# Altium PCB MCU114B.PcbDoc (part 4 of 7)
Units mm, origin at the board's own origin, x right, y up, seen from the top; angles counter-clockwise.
Board outline 105.51 x 58.76 mm, 8 copper layers (Top Layer, GND 2, Signal Layer 3, Power 4, Power 5, Signal Layer 6, GND 7, Bottom), stack 1.554 mm thick; 444 components, 418 nets, 1811 pads, 981 vias.
Unrouted connection lines stored in the file: 3.
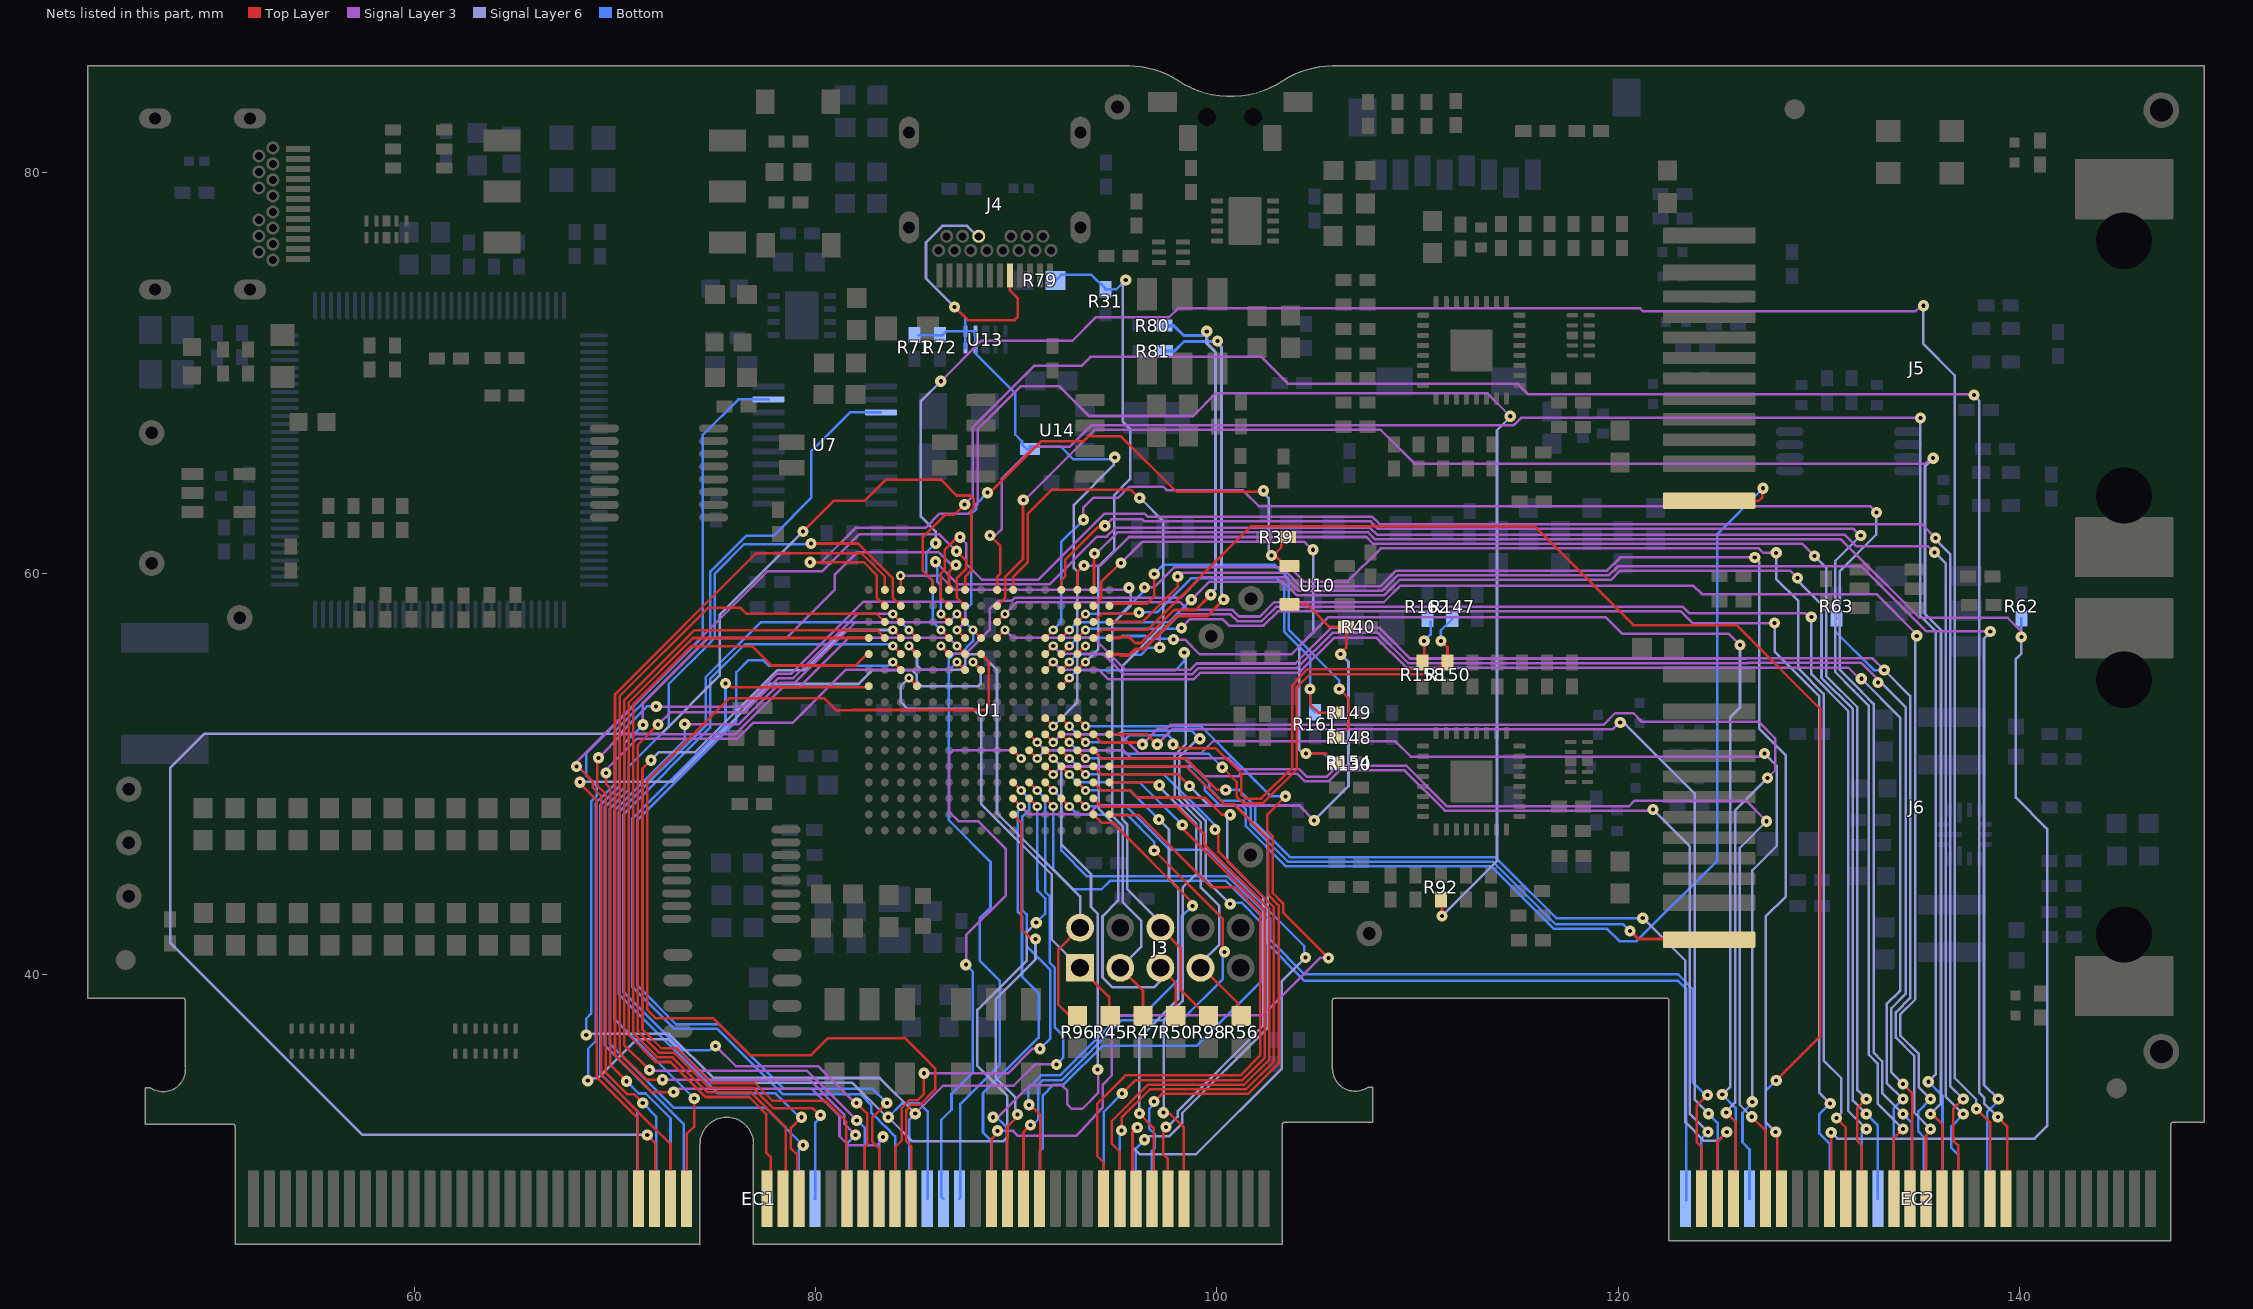
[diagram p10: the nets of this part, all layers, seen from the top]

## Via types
v1: diameter 0.559, hole 0.203, Top Layer to Bottom, tented both sides, 810 vias
v2: diameter 0.457, hole 0.203, Top Layer to Bottom, tented both sides, 153 vias
v3: diameter 0.5, hole 0.2, Top Layer to Bottom, tented both sides, 10 vias
v4: diameter 0.5, hole 0.2, Top Layer to Bottom, tented bottom, 4 vias
v5: diameter 0.5, hole 0.2, Top Layer to Bottom, tented top, 4 vias

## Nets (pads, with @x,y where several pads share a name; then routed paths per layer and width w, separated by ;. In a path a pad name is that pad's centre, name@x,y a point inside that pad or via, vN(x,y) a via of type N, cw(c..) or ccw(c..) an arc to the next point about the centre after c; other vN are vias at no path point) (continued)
MCU_D_N: R81.2 U1.E16 | length 22.7
  Top Layer w0.155: U1.E16@94.641,55.995 95.12,55.995 95.178,55.936 95.61,55.936 95.915,56.241 96.346,56.241 97.989,57.884 99.51,57.884 v1(100.337,58.711)
  Signal Layer 6 w0.155: v1(100.025,71.603) 100.025,71.493 100.236,71.283 100.236,59.004 100.259,58.98 100.259,58.788 v1(100.337,58.711)
  Bottom w0.155: R81.2@97.399,71.099 97.877,71.099 98.356,71.578 100.001,71.578 v1(100.025,71.603)
MCU_D_P: R80.2 U1.D16 | length 22
  Top Layer w0.155: U1.D16@94.641,56.795 95.127,56.795 95.185,56.853 95.61,56.853 95.915,56.549 96.219,56.549 97.862,58.191 98.933,58.191 v1(99.695,58.953)
  Signal Layer 6 w0.155: v1(99.492,72.085) 99.492,71.488 99.835,71.144 99.838,71.144 99.928,71.053 99.928,59.246 99.695,59.013 v1(99.695,58.953)
  Bottom w0.155: R80.2@97.374,72.365 97.851,72.365 98.33,71.886 99.292,71.886 v1(99.492,72.085)
MCU_GPIO0: EC1.49 U1.F8 | length 46.6
  Top Layer w0.127: v1(68.25,49.606) 68.25,49.545 69.075,48.719 69.075,34.907 71.121,32.861 71.121,28.872 EC1.49@71.157,28.836 ; v2(87.841,55.595) U1.F8@88.241,55.195
  Signal Layer 6 w0.127: v1(68.25,49.606) 68.263,49.619 72.829,49.619 77.712,54.503 82.138,54.503 82.824,55.189 84.804,55.189 85.035,54.958 85.035,54.644 85.291,54.389 88.103,54.389 88.235,54.52 88.235,55.201 v2(87.841,55.595)
MCU_GPIO1: EC1.51 U1.A7 | length 92.8
  Top Layer w0.127: v1(71.598,32.02) 71.992,31.627 71.992,28.836 EC1.51@71.957,28.836 ; v1(79.366,62.106) 80.892,63.631 82.436,63.631 83.499,64.694 86.233,64.694 87.026,63.901 87.691,63.901 87.867,63.725 87.867,63.252 87.748,63.133 87.748,60.152 87.441,59.845 U1.A7@87.441,59.195
  Signal Layer 6 w0.127: v1(71.598,32.02) 57.401,32.02 47.803,41.619 47.803,50.317 49.505,52.019 72.314,52.019 75.209,54.915 75.209,57.949 v1(79.366,62.106)
MCU_GPIO2: EC1.53 U1.B7 | length 51.1
  Top Layer w0.127: v1(68.072,50.394) 68.135,50.394 68.872,49.657 68.872,49.352 69.304,48.92 69.304,35.002 71.96,32.346 71.972,32.346 72.757,31.561 EC1.53@72.757,28.836 ; v1(87.016,61.119) 87.511,60.624 87.511,60.268 87.034,59.791 87.034,58.802 U1.B7@87.441,58.395
  Signal Layer 3 w0.127: v1(68.072,50.394) 68.072,50.608 77.581,60.118 80.311,60.118 82.156,61.963 86.163,61.963 87.007,61.119 v1(87.016,61.119)
MCU_GPIO3: EC1.55 U1.C7 | length 43.4
  Top Layer w0.127: EC1.55@73.557,28.836 73.557,32.056 73.939,32.439 v1(73.939,33.833) ; v2(87.041,57.995) U1.C7@87.441,57.595
  Signal Layer 3 w0.127: v1(73.464,52.497) 76.166,52.497 78.235,54.566 78.971,54.566 81.993,57.589 86.635,57.589 v2(87.041,57.995)
  Bottom w0.127: v1(73.464,52.497) 73.464,51.698 69.945,48.179 69.945,37.827 v1(73.939,33.833)
MCU_GPIO4: EC1.50 U1.D7 | length 46.4
  Top Layer w0.127: v2(87.041,57.195) U1.D7@87.441,56.795
  Signal Layer 3 w0.127: v1@72.009,53.365 76.388,53.365 78.046,55.023 78.781,55.023 82.356,58.598 87.238,58.598 87.448,58.389 87.448,57.832 87.449,57.83 87.449,57.603 v2(87.041,57.195)
  Bottom w0.127: EC1.50@71.157,28.836 71.093,28.9 71.093,33.225 69.259,35.059 69.259,48.463 70.218,49.423 70.218,52.019 71.581,53.382 v1(72.041,53.382)
MCU_GPIO5: EC1.52 U1.E7 | length 44.6
  Top Layer w0.127: v1(69.165,50.82) 69.101,50.756 69.101,49.447 69.533,49.015 69.533,35.096 70.577,34.052 70.926,34.052 v1(71.374,33.604) ; v2(87.041,56.395) U1.E7@87.441,55.995
  Signal Layer 3 w0.127: v1(69.165,50.82) 70.346,52.001 70.775,52.001 75.993,52.001 78.33,54.337 79.168,54.337 81.631,56.801 83.678,56.801 86.635,56.801 v2(87.041,56.395)
  Bottom w0.127: v1(71.374,33.604) 72.043,32.935 72.043,28.922 EC1.52@71.957,28.836
MCU_GPIO6: EC1.54 U1.F7 | length 43.2
  Top Layer w0.127: v1(69.545,50.063) 69.545,49.505 69.761,49.289 69.761,35.712 69.761,35.496 v1(70.561,34.696) ; v2(87.041,55.595) U1.F7@87.441,55.195
  Signal Layer 3 w0.127: v1(69.545,50.063) 69.545,50.227 71.09,51.772 76.088,51.772 76.875,52.559 78.848,52.559 81.49,55.201 86.648,55.201 v2(87.041,55.595)
  Bottom w0.127: v1(70.561,34.696) 71.174,34.084 71.523,34.084 72.757,32.85 EC1.54@72.757,28.836
MCU_GPIO7: EC1.56 U1.A6 | length 48
  Top Layer w0.127: U1.A6@86.641,59.195 86.641,60.084 v1(86.991,60.433)
  Signal Layer 3 w0.127: v1(71.38,52.468) 71.38,53.55 74.626,56.795 78.537,56.795 80.95,59.207 80.95,59.967 82.044,61.062 86.142,61.062 86.688,60.516 86.908,60.516 v1(86.991,60.433)
  Bottom w0.127: v1(71.38,52.468) 70.447,51.534 70.447,49.328 69.488,48.369 69.488,36.481 73.406,32.563 73.406,28.987 EC1.56@73.557,28.836
MCU_GPIO8: EC1.57 U1.D1 | length 42.8
  Top Layer w0.127: EC1.57@77.557,28.836 77.749,29.028 77.749,30.928 77.524,31.153 77.524,33.067 76.683,33.909 74.51,33.909 72.765,35.655 72.01,35.655 70.675,36.989 70.675,50.563 70.675,53.588 73.882,56.795 U1.D1@82.641,56.795
MCU_GPIO9: EC1.59 U1.E1 | length 43.1
  Top Layer w0.127: EC1.59@78.357,28.836 78.494,28.973 78.494,32.42 76.777,34.138 74.605,34.138 72.859,35.883 72.105,35.883 70.904,37.084 70.904,50.469 70.904,53.494 73.799,56.388 76.817,56.388 77.783,55.423 81.835,55.423 81.986,55.423 82.45,55.888 82.461,55.888 82.568,55.995 U1.E1@82.641,55.995
MCU_GPIO10: EC1.61 U1.D4 | length 45.7
  Top Layer w0.127: EC1.61@79.157,28.836 79.066,28.927 79.066,31.046 78.761,31.35 78.761,31.456 78.761,32.366 v1(79.295,32.9) ; v2(84.641,57.195) U1.D4@85.041,56.795
  Bottom w0.127: v1(79.295,32.9) 79.178,32.9 77.991,34.087 75.133,34.087 70.173,39.047 70.173,48.085 74.507,52.418 74.507,54.838 77.257,57.589 84.248,57.589 v2(84.641,57.195)
MCU_GPIO11: J3.2 R96.2 U1.E4 | length 26.6
  Top Layer w0.127: v2(84.641,56.395) U1.E4@85.041,55.995 ; R96.2@93.051,38.041 92.569,38.041 92.1,38.509 92.1,41.271 J3.2@93.18,42.351
  Signal Layer 6 w0.127: v2(84.641,56.395) 85.048,55.989 85.048,55.432 85.278,55.201 85.835,55.201 87.204,55.201 87.448,55.444 87.448,55.758 87.678,55.989 88.248,55.989 89.035,55.201 89.035,48.056 93.18,43.911 J3.2@93.18,42.351
MCU_GPIO12: J3.1 R45.1 U1.G4 | length 23.7
  Top Layer w0.127: v2(84.641,54.795) U1.G4@85.041,54.395 ; J3.1@93.18,40.351 94.63,38.902 R45.1@94.63,38.079
  Signal Layer 6 w0.127: v2(84.641,54.795) 84.241,54.395 84.241,53.595 84.571,53.265 87.829,53.265 88.248,52.846 88.248,48.521 91.766,45.002 91.766,41.766 J3.1@93.18,40.351
MCU_GPIO13: J3.3 R47.1 U1.A3 | length 35.6
  Top Layer w0.127: v2(84.226,59.899) 84.226,59.211 U1.A3@84.241,59.195 ; J3.3@95.18,40.351 96.316,39.216 R47.1@96.316,37.942
  Signal Layer 3 w0.127: v2(84.226,59.899) 86.205,59.899 86.907,59.197 95.511,59.197 v1(95.611,59.298)
  Signal Layer 6 w0.127: J3.3@95.18,40.351 96.236,41.407 96.236,42.696 95.299,43.633 95.299,47.418 94.775,47.942 94.775,57.479 95.698,58.401 v1@95.698,59.219
MCU_GPIO14: EC1.62 U1.B3 | length 51.8
  Top Layer w0.127: v1(79.765,61.508) 82.107,61.508 83.832,59.782 83.832,58.804 U1.B3@84.241,58.395
  Bottom w0.127: EC1.62@79.157,28.836 79.157,31.289 v1(79.371,31.503) 77.498,33.376 72.916,33.376 69.716,36.576 69.716,48.274 70.675,49.233 70.675,50.381 72.668,52.374 72.668,53.999 72.669,54 72.669,54.502 74.739,56.572 74.739,56.585 74.968,56.814 74.968,60.008 76.434,61.474 79.682,61.474 v1@79.698,61.458
MCU_GPIO15: EC1.64 U1.C3 | length 45.4
  Top Layer w0.127: v1(72.136,52.476) 71.133,51.473 71.133,50.374 71.133,37.179 72.199,36.112 72.954,36.112 74.7,34.366 76.872,34.366 77.894,33.344 79.86,33.344 80.203,33.001 v1(80.234,33.001) ; v2(83.841,57.995) U1.C3@84.241,57.595
  Signal Layer 3 w0.127: v1(72.136,52.476) 72.746,53.086 76.432,53.086 78.14,54.795 78.876,54.795 82.076,57.995 v2(83.841,57.995)
  Bottom w0.127: EC1.64@79.957,28.836 79.968,28.846 79.968,32.618 80.234,32.885 v1(80.234,33.001)
MCU_GPIO16: EC1.67 U1.D3 | length 44.8
  Top Layer w0.127: v1(71.78,50.698) 71.361,50.279 71.361,37.273 72.294,36.341 73.049,36.341 74.794,34.595 76.967,34.595 77.83,33.731 80.47,33.731 81.527,32.674 81.527,28.866 EC1.67@81.557,28.836 ; v2(83.841,57.195) U1.D3@84.241,56.795
  Signal Layer 6 w0.127: v1(71.78,50.698) 72.187,51.105 73.991,51.105 78.081,55.194 79.452,55.194 81.453,57.195 v2(83.841,57.195)
MCU_GPIO17: EC1.69 U1.E3 | length 47
  Top Layer w0.127: v1(82.038,33.611) 82.558,33.09 82.558,31.554 82.431,31.427 82.431,28.91 EC1.69@82.357,28.836 ; v2(83.841,56.395) U1.E3@84.241,55.995
  Signal Layer 3 w0.127: v1(75.006,36.449) 76.01,35.446 80.113,35.446 81.948,33.611 v1(82.038,33.611)
  Bottom w0.127: v1(75.006,36.449) 74.919,36.449 74.716,36.246 73.297,36.246 70.402,39.141 70.402,47.99 74.735,52.323 74.735,54.743 76.476,56.484 83.602,56.484 83.628,56.458 83.778,56.458 v2(83.841,56.395)
MCU_GPIO18: EC1.71 U1.F3 | length 46.5
  Top Layer w0.127: EC1.71@83.157,28.836 83.157,31.337 82.825,31.668 82.825,32.889 v1(83.541,33.604) ; v2(83.841,55.595) U1.F3@84.241,55.195
  Bottom w0.127: v1(83.541,33.604) 82.835,34.31 78.415,34.31 75.189,37.535 73.043,37.535 71.088,39.491 71.088,47.706 76.043,52.661 76.043,55.088 76.651,55.696 77.37,55.696 77.65,55.417 83.602,55.417 83.78,55.595 v2(83.841,55.595)
MCU_GPIO19: R92.2 U1.B2 | length 74.7
  Top Layer w0.127: v1(79.722,60.571) 82.396,60.571 83.051,59.917 83.051,59.033 83.051,58.785 U1.B2@83.441,58.395
  Top Layer w0.159: v1(111.222,42.933) 111.222,43.741 R92.2@111.247,43.766
  Signal Layer 3 w0.127: v1(79.722,60.571) 80.273,60.571 81.982,62.281 85.46,62.281 86.178,62.999 87.614,62.999 88.07,63.455 88.07,67.191 90.217,69.338 92.149,69.338 93.624,67.863 98.821,67.863 99.964,69.006 113.47,69.006 v1(114.626,67.85)
  Signal Layer 6 w0.127: v1(111.222,42.933) 113.966,45.676 113.966,67.154 114.626,67.814 v1(114.626,67.85)
MCU_GPIO20: EC1.68 U1.C2 | length 50.2
  Top Layer w0.127: v1(72.365,34.773) 71.552,34.773 70.293,36.032 70.218,36.106 70.218,53.778 70.224,53.783 70.224,53.892 74.625,58.293 76.251,58.293 76.539,58.004 83.032,58.004 U1.C2@83.441,57.595
  Signal Layer 3 w0.127: v1(72.365,34.773) 79.681,34.773 81.41,33.043 81.41,32.588 v1(81.986,32.011)
  Bottom w0.127: EC1.68@81.557,28.836 81.557,31.582 v1(81.986,32.011)
MCU_GPIO21: EC1.70 U1.D2 | length 49.1
  Top Layer w0.127: v1(71.704,35.255) 70.447,36.513 70.447,53.683 73.949,57.185 83.051,57.185 U1.D2@83.441,56.795
  Signal Layer 3 w0.127: v1(71.704,35.255) 71.742,35.217 79.56,35.217 80.15,34.627 v1(82.044,32.733)
  Bottom w0.127: v1(82.044,32.733) 82.091,32.733 82.431,32.392 82.431,28.91 EC1.70@82.357,28.836
MCU_GPIO22: EC1.72 U1.A2 | length 54.8
  Top Layer w0.127: v1(72.914,34.157) 71.844,34.157 69.99,36.011 69.99,36.614 69.99,53.981 77.031,61.023 82.268,61.023 83.441,59.849 U1.A2@83.441,59.195
  Signal Layer 3 w0.127: v1(72.914,34.157) 73.031,34.157 73.19,34.315 79.815,34.315 81.182,32.948 81.182,31.952 81.631,31.503 83.029,31.503 83.347,31.821 v1(83.347,31.923)
  Bottom w0.127: EC1.72@83.157,28.836 83.157,31.733 v1(83.347,31.923)
MCU_GPIO23: EC1.74 U1.G1 | length 43.8
  Top Layer w0.127: v1(75.499,54.53) 75.616,54.53 75.811,54.335 82.431,54.335 82.438,54.343 82.589,54.343 U1.G1@82.641,54.395
  Bottom w0.127: v1(75.499,54.53) 75.499,52.44 70.859,47.8 70.859,39.396 72.949,37.307 75.094,37.307 78.345,34.056 82.222,34.056 82.758,33.519 82.758,33.14 83.168,32.73 83.168,32.716 83.428,32.455 83.443,32.455 83.957,31.941 EC1.74@83.957,28.836
MCU_GPIO24: EC1.75 U1.E8 | length 56.9
  Top Layer w0.127: EC1.75@84.757,28.836 84.757,31.451 84.514,31.693 84.514,33.262 84.775,33.522 85.186,33.522 85.954,34.29 85.954,35.336 85.389,35.9 84.447,36.842 80.607,36.842 79.763,35.999 76.727,35.999 74.892,37.833 72.033,37.833 71.59,38.277 71.59,49.695 75.694,53.799 80.415,53.799 81.012,53.201 81.83,53.201 81.833,53.204 88.403,53.204 88.632,53.433 88.632,55.604 U1.E8@88.241,55.995
MCU_GPIO25: J3.6 R98.2 U1.A10 | length 39.3
  Top Layer w0.127: U1.A10@89.841,59.195 89.841,59.845 90.559,60.563 90.559,62.967 91.785,64.193 95.693,64.193 v1@96.197,63.689 ; J3.6@97.18,42.351 98.208,41.324 98.208,39.244 R98.2@99.372,38.079
  Signal Layer 6 w0.127: v1@96.197,63.689 96.258,63.689 97.319,62.628 97.319,57.43 95.291,55.402 95.291,47.749 95.528,47.513 95.528,44.274 96.94,42.861 96.94,42.315 J3.6@97.166,42.089
  other v1: 96.15,63.779
MCU_GPIO26: J3.5 R50.1 U1.L11 | length 22.3
  Top Layer w0.127: U1.L11@90.641,51.195 v2(91.041,50.795) ; J3.5@97.18,40.351 97.949,39.583 R50.1@97.949,37.942
  Signal Layer 6 w0.127: v2(91.041,50.795) 91.448,51.201 93.848,51.201 94.115,50.934 94.115,48.279 95.071,47.324 95.071,43.696 94.295,42.92 94.295,39.868 94.786,39.377 96.871,39.377 97.18,39.686 J3.5@97.18,40.351
MCU_GPIO27: J3.7 R56.1 U1.G13 | length 27.9
  Top Layer w0.127: U1.G13@92.241,54.395 v2(92.641,54.795) ; J3.7@99.18,40.351 99.275,40.351 101.069,38.558 101.069,38.088 R56.1@101.215,37.942
  Signal Layer 6 w0.127: v1(98.37,56.065) 98.448,55.986 98.448,51.501 97.892,50.944 97.892,48.923 98.256,48.559 99.205,47.61 99.205,44.355 100.123,43.438 100.123,42.552 ; J3.7@99.166,40.089 99.166,40.565 100.122,41.521 100.122,42.551
  Bottom w0.127: v2(92.641,54.795) 93.033,55.187 93.277,55.187 93.278,55.189 97.297,55.189 ; 97.297,55.188 97.93,55.188 98.37,55.628 v1(98.37,56.065)
MCU_GPIO28: EC1.76 U1.N11 U7.9 | length 82.2
  Top Layer w0.127: U1.N11@90.641,49.595 v2(91.041,49.195)
  Signal Layer 3 w0.127: v1(84.959,33.078) 86.352,34.471 89.865,34.471 90.929,35.535 v1(91.999,35.535)
  Signal Layer 6 w0.127: v1(68.555,37.008) 68.605,37.059 72.69,37.059 74.893,34.856 83.181,34.856 v1(84.959,33.078)
  Bottom w0.127: v1(68.555,37.008) 68.555,37.816 68.802,38.063 68.802,48.653 69.075,48.926 69.075,49.409 68.555,49.93 68.555,51.047 74.371,56.864 74.371,66.929 76.138,68.696 U7.9@77.642,68.696 ; EC1.76@84.757,28.836 84.667,28.926 84.667,32.786 v1(84.959,33.078) ; v2(91.041,49.195) 91.435,48.801 91.435,44.772 ; 91.437,44.772 91.437,44.144 91.67,43.911 91.67,40.598 91.923,40.345 91.923,37.373 92.342,36.953 92.342,35.878 v1(91.999,35.535)
MCU_GPIO29: EC1.78 U1.P11 U7.13 | length 90.8
  Top Layer w0.127: U1.P11@90.641,48.795 v2(91.041,48.395)
  Signal Layer 6 w0.127: v1@68.656,34.849 69.134,34.849 71.065,36.779 72.647,36.779 74.799,34.627 81.815,34.627 83.543,32.9 v1(83.613,32.9) 84.819,31.693 85.956,31.693 89.331,31.693 89.557,31.92 89.557,33.964 88.062,35.459 88.062,38.252 90.51,40.701 90.51,42.118 v1(90.992,42.6)
  Bottom w0.127: v1@68.656,34.849 68.656,36.322 69.03,36.696 69.03,48.558 69.99,49.517 69.99,52.159 74.739,56.909 74.739,60.102 76.528,61.891 77.881,61.891 79.781,63.791 79.781,66.116 81.711,68.046 U7.13@83.242,68.046 ; v1(83.613,32.9) 84.298,33.586 85.188,33.586 85.581,33.192 85.581,32.005 85.581,28.86 EC1.78@85.557,28.836 ; v1(90.992,42.6) 91.441,43.049 91.441,43.816 91.056,44.202 91.056,44.711 91.05,44.717 91.05,48.386 v2(91.041,48.395)
  other v1: 68.631,34.722
MCU_GPIO30: EC1.80 U1.L10 | length 30
  Top Layer w0.127: U1.L10@89.841,51.195 v2(90.241,50.795)
  Signal Layer 3 w0.127: v1@87.499,40.469 87.499,41.983 89.48,43.964 89.48,46.267 88.083,47.664 87.11,47.664 86.648,48.126 86.648,50.996 86.841,51.189 89.848,51.189 v2(90.241,50.795)
  Bottom w0.127: EC1.80@86.357,28.836 86.256,28.937 86.256,32.764 86.766,33.274 86.766,34.061 87.833,35.128 87.833,40.155 v1(87.481,40.507)
MCU_GPIO31: EC1.82 R39.1 U1.D8 U10.1 | length 61.2
  Top Layer w0.127: v2(87.841,57.195) U1.D8@88.241,56.795 ; v1(88.566,64.04) 88.691,64.04 91.257,66.607 93.347,66.607 93.593,66.853 95.227,66.853 97.992,64.087 102.271,64.087 v1(102.325,64.141) ; v1(102.718,60.909) v1@102.808,60.909 ; R39.1@103.543,61.689 103.444,61.689 103.208,61.452 103.208,61.309 v1@102.808,60.909 ; U10.1@103.625,60.378 103.425,60.378 102.977,60.827 102.891,60.827 v1@102.808,60.909
  Signal Layer 6 w0.127: v1(102.325,64.141) 102.325,64.024 102.593,63.756 102.593,61.151 102.718,61.026 v1(102.718,60.909)
  Bottom w0.127: EC1.82@87.157,28.836 87.207,28.885 87.207,33.562 89.179,35.535 89.179,36.829 ; v1(88.566,64.04) 88.007,63.481 88.007,63.227 87.753,62.973 87.753,58.477 87.448,58.172 87.448,57.589 v2(87.841,57.195) 87.841,56.638 87.204,56.001 86.891,56.001 86.635,55.745 86.635,47.708 88.712,45.631 88.712,43.363 88.185,42.836 88.185,40.695 89.179,39.7 89.179,39.588 ; 89.18,36.83 89.18,39.587
MCU_GPIO32: EC1.85 U1.J14 | length 47.9
  Top Layer w0.127: EC1.85@88.784,28.923 88.784,31.84 89.065,32.121 v1(89.065,32.224) ; U1.J14@93.041,52.795 v2(93.441,52.395) ; v1@103.577,49.054 102.514,47.992 102.514,47.177 102.794,46.897 102.794,44.069 103.302,43.561 103.302,43.104 v1(105.56,40.846)
  Signal Layer 3 w0.127: v1(89.065,32.224) 89.071,32.217 89.832,32.217 90.077,31.973 92.984,31.973 93.218,32.207 94.277,33.356 94.31,33.393 94.31,34.537 94.767,34.994 94.767,37.578 95.17,37.98 102.282,37.98 105.147,40.846 v1(105.56,40.846)
  Bottom w0.127: v2(93.441,52.395) 99.2,52.395 101.248,50.347 101.248,50.339 101.896,49.691 101.905,49.691 102.694,48.902 v1@103.526,48.902
  other v1: 103.425,48.902
MCU_GPIO33: EC1.87 U1.R10 | length 21.4
  Top Layer w0.127: EC1.87@89.557,28.836 89.557,32.432 v1@90.173,33.048 ; U1.R10@89.841,47.995 90.241,47.595 90.241,42.298 v1@90.852,41.688
  Signal Layer 6 w0.127: v1@90.139,33.04 90.139,33.132 89.941,33.33 89.941,33.903 88.984,34.86 88.984,38.794 90.955,40.764 v1(90.955,41.792) ; v1@90.189,33.131 v1@90.267,33.052
  other v1: 90.061,33.039
MCU_GPIO34: EC1.86 R40.1 U1.P10 U10.3 | length 51.1
  Top Layer w0.127: U1.P10@89.841,48.795 v2(90.241,48.395) ; U10.3@103.625,58.478 104.499,58.478 105.624,57.353 R40.1@106.443,57.353 106.443,56.318 106.172,56.048 v1(106.172,55.989)
  Signal Layer 3 w0.127: v2(90.241,48.395) 90.635,48.001 93.604,48.001 94.048,48.445 104.108,48.445 v1(104.851,47.701)
  Signal Layer 6 w0.127: v1(104.851,47.701) 106.561,49.411 106.561,55.6 v1(106.172,55.989)
  Bottom w0.127: EC1.86@88.757,28.836 88.757,31.72 88.338,32.139 88.338,34.098 91.11,36.87 91.11,39.091 90.282,39.919 90.282,42.921 90.076,43.126 90.076,48.155 90.241,48.32 v2(90.241,48.395)
MCU_GPIO35: EC1.73 U1.N10 | length 27.9
  Top Layer w0.127: EC1.73@83.957,28.836 83.957,31.416 84.286,31.744 84.286,33.356 84.68,33.751 85.091,33.751 85.389,34.049 v1(85.389,35.092) ; U1.N10@89.841,49.595 v2(90.241,49.195)
  Signal Layer 3 w0.127: v1(85.389,35.092) 89.575,35.092 90.787,36.304 91.173,36.304 v1(91.183,36.314)
  Bottom w0.127: v2(90.241,49.195) 90.635,48.801 90.635,48.558 90.635,48.232 90.305,47.902 90.305,43.221 90.51,43.015 90.51,42.311 90.51,41.434 91.694,40.25 91.694,36.825 v1(91.183,36.314)
MCU_GPIO36: EC2.122 U1.P12 | length 49.2
  Top Layer w0.127: U1.P12@91.441,48.795 v2(91.841,48.395)
  Bottom w0.127: v2(91.841,48.395) 91.841,45.25 92.815,44.277 94.259,44.277 94.666,44.683 100.462,44.683 102.438,42.707 102.438,41.637 104.375,39.7 123.001,39.7 123.39,39.311 EC2.122@123.39,28.77
MCU_GPIO37: EC2.123 U1.N12 | length 49.8
  Top Layer w0.127: U1.N12@91.441,49.595 v2(91.841,49.195) ; EC2.123@124.182,28.923 124.182,31.396 123.922,31.655 123.922,33.473 v1(124.46,34.011)
  Bottom w0.127: v2(91.841,49.195) 92.241,48.795 92.241,46.196 93.526,44.912 100.556,44.912 102.667,42.802 102.667,41.732 104.377,40.022 123.002,40.022 123.719,39.305 123.719,34.659 124.368,34.011 v1(124.46,34.011)
MCU_GPIO38: EC2.124 U1.M12 | length 52.6
  Top Layer w0.127: U1.M12@91.441,50.395 v2(91.841,49.995)
  Signal Layer 3 w0.127: v2(91.841,49.995) 92.235,50.389 98.845,50.389 99.329,49.905 101.082,49.905 101.209,50.032 104.001,50.032 104.387,49.647 105.553,49.647 106.104,50.197 109.354,50.197 111.363,48.189 121.482,48.189 v1@121.509,48.216
  Signal Layer 6 w0.127: v1(121.738,48.241) 123.585,46.394 123.585,33.059 v1(124.481,32.163)
  Bottom w0.127: EC2.124@124.155,28.836 124.155,31.837 v1(124.481,32.163)
MCU_GPIO39: EC1.88 U1.L12 | length 29.5
  Top Layer w0.127: U1.L12@91.441,51.195 v2(91.841,50.795)
  Signal Layer 3 w0.127: v1@89.058,32.911 89.086,32.911 90.663,34.487 92.28,34.487 92.541,34.227 92.541,33.545 92.761,33.325 93.294,33.325 94.082,34.112 94.082,35.255 v1(94.056,35.281)
  Signal Layer 6 w0.127: v2(91.841,50.795) 92.248,50.389 92.248,46.493 93.722,45.019 93.722,43.386 94.066,43.042 94.066,35.29 v1(94.056,35.281)
  Bottom w0.127: v1(88.838,32.901) 89.016,32.901 89.382,32.535 89.521,32.397 89.521,28.872 EC1.88@89.557,28.836
MCU_GPIO40: EC1.89 U1.P13 | length 31.3
  Top Layer w0.127: EC1.89@90.357,28.836 90.357,32.163 v1(90.707,32.512) ; U1.P13@92.241,48.795 v2(92.641,48.395) ; v1(96.876,46.203) 100.295,42.783 100.295,41.438 100.298,41.435 100.298,41.231 v1(100.381,41.148)
  Bottom w0.127: v1@90.759,32.459 91.093,32.793 91.093,34.518 91.329,34.754 92.267,34.754 95.252,37.739 98.246,37.739 100.295,39.788 100.295,41.062 v1(100.381,41.148) ; v2(92.641,48.395) 93.049,47.987 95.523,47.987 96.876,46.634 v1(96.876,46.203)
MCU_GPIO41: EC1.91 U1.R15 | length 26.2
  Top Layer w0.127: v1@90.567,33.642 91.194,33.015 91.194,28.873 EC1.91@91.157,28.836 ; U1.R15@93.841,47.995 94.251,47.585 94.803,47.585 v1@98.694,43.695
  Bottom w0.127: v1@90.594,33.535 90.594,34.342 91.235,34.983 92.172,34.983 95.158,37.968 96.297,37.968 98.236,39.907 98.236,42.901 v1(98.776,43.441)
  other v1: 90.625,33.519
MCU_GPIO44: J4.A5 J4.B5 R71.2 R72.2 U1.J12 U13.4 U13.5 U13.6 U13.7 U14.4 | length 44.9
  Top Layer w0.127: v1(86.919,73.304) 87.579,72.644 89.916,72.644 90.068,72.796 90.068,73.736 89.675,74.129 J4.A5@89.675,74.866 ; U1.J12@91.441,52.795 v2(91.841,52.395)
  Signal Layer 6 w0.127: v1(86.919,73.304) 85.496,74.727 85.496,76.526 86.161,77.19 86.312,77.341 87.539,77.341 88.054,76.826 J4.B5@88.125,76.826 ; v2(91.841,52.395) 93.048,53.601 93.048,60.098 92.871,60.275 92.871,63.432 94.854,65.416 94.854,65.695 v1@94.92,65.761
  Bottom w0.127: R71.2@85.105,71.896 86.324,71.896 86.513,72.085 U13.6@87.46,72.085 ; v1(86.919,73.304) 87.46,72.763 U13.6@87.46,72.085 ; U13.5@87.46,71.25 U13.6@87.46,72.085 ; U14.4@90.518,66.208 90.282,66.444 90.282,66.6 89.954,66.928 89.954,68.993 87.997,70.95 87.997,71.214 U13.4@87.96,71.25 U13.7@87.96,72.085 U13.6@87.46,72.085 ; U14.4@90.675,66.208 90.675,66.332 92.215,66.332 92.83,65.717 94.876,65.717 v1@94.92,65.761
  other v1: 94.907,65.802
MCU_GPIO45: EC1.92 U1.J13 | length 40.6
  Top Layer w0.127: U1.J13@92.241,52.795 v2(92.641,52.395)
  Signal Layer 6 w0.127: v1(99.147,51.768) 99.038,51.768 98.12,50.85 98.12,49.018 99.434,47.704 99.434,44.762 v1(100.66,43.536)
  Bottom w0.127: EC1.92@91.157,28.836 91.157,31.206 91.321,31.37 91.321,33.994 91.853,34.525 92.362,34.525 94.311,36.474 99.009,36.474 102.177,39.642 102.177,42.645 101.219,43.603 100.727,43.603 v1(100.66,43.536) ; v2(92.641,52.395) 93.035,52.001 95.126,52.001 95.291,52.166 98.749,52.166 v1(99.147,51.768)
MCU_GPIO46: R31.2 R79.1 U1.F14 | length 24.9
  Top Layer w0.127: U1.F14@93.041,55.195 v2(93.441,55.595)
  Signal Layer 6 w0.127: v2(93.441,55.595) 94.077,56.231 94.077,60.343 94.872,61.138 94.872,63.909 95.678,64.715 95.678,67.208 95.311,67.574 95.311,68.546 95.313,68.548 95.313,68.917 95.311,68.919 95.311,74.392 95.453,74.534 v1(95.453,74.651)
  Bottom w0.127: R79.1@91.956,74.621 92.24,74.905 93.744,74.905 94.437,74.211 R31.2@94.437,74.184 94.986,74.184 v1(95.453,74.651)
MCU_GPIO47: U1.E14 | length 0.6
  Top Layer w0.127: U1.E14@93.041,55.995 v2(93.441,56.395)
MCU_GPIO48: EC1.99 U1.R16 | length 30.7
  Top Layer w0.127: EC1.99@94.357,28.836 94.357,30.636 94.037,30.956 94.037,33.578 95.442,34.983 101.174,34.983 102.159,35.968 102.159,43.087 100.872,44.374 99.709,44.374 96.121,47.962 94.674,47.962 U1.R16@94.641,47.995
MCU_GPIO49: EC1.101 U1.P15 | length 32
  Top Layer w0.127: U1.P15@93.841,48.795 94.251,48.385 97.995,48.385 99.361,47.02 99.361,46.532 102.616,43.277 102.616,35.779 101.363,34.525 96.567,34.525 94.767,32.726 94.767,31.575 95.157,31.185 EC1.101@95.157,28.836
MCU_GPIO50: EC1.103 U1.P14 | length 35.1
  Top Layer w0.127: U1.P14@93.041,48.795 v2(93.441,48.395) ; EC1.103@95.957,28.836 95.792,29.001 95.792,32.151 v1(96.033,32.392)
  Signal Layer 6 w0.127: v1(96.033,32.392) 96.033,32.33 95.805,32.102 95.805,31.401 96.147,31.058 97.385,31.058 97.703,31.058 98.971,31.058 103.226,35.313 103.226,39.675 v1(104.419,40.869)
  Bottom w0.127: v2(93.441,48.395) 95.496,48.395 97.661,46.23 99.562,46.23 104.355,41.437 104.355,40.933 v1(104.419,40.869)
MCU_GPIO51: EC1.105 U1.N14 | length 25.3
  Top Layer w0.127: U1.N14@93.041,49.595 v2(93.441,49.195) ; v1(96.137,33.087) 96.137,33.075 96.849,32.363 96.849,28.928 EC1.105@96.757,28.836
  Signal Layer 6 w0.127: v1(96.137,33.087) 96.137,36.858 98.066,38.786 98.066,44.323 97.612,44.776 97.612,47.244 v1(97.104,47.752)
  Bottom w0.127: v2(93.441,49.195) 95.661,49.195 96.519,48.337 v1(97.104,47.752)
MCU_GPIO52: EC1.107 U1.N15 | length 29.5
  Top Layer w0.127: U1.N15@93.841,49.595 94.241,49.195 95.687,49.195 96.039,48.843 98.766,48.843 98.77,48.838 99.399,48.838 100.254,47.983 v1(100.661,47.983) ; v1(97.456,32.417) 97.456,32.3 97.318,32.163 97.318,31.056 97.557,30.817 EC1.107@97.557,28.836
  Signal Layer 6 w0.127: v1(97.456,32.417) 97.531,32.417 98.04,32.926 98.04,33.194 102.311,37.465 102.311,43.887 100.514,45.684 100.514,47.862 v1@100.465,47.911
MCU_GPIO53: EC1.109 U1.N16 | length 25.2
  Top Layer w0.127: U1.N16@94.641,49.595 96.872,49.595 97.013,49.454 v1(97.13,49.454) ; v1(97.329,33.128) 97.394,33.063 97.674,33.063 98.357,32.38 EC1.109@98.357,28.836
  Signal Layer 6 w0.127: v1(97.13,49.454) 97.13,49.362 98.977,47.515 98.977,45.041 98.295,44.359 98.295,38.692 97.347,37.745 97.347,33.147 v1(97.329,33.128)
MCU_GPIO54: EC1.100 U1.M13 | length 34
  Top Layer w0.127: U1.M13@92.241,50.395 v2(92.641,49.995) ; v1(95.275,34.087) 95.943,34.754 101.268,34.754 102.387,35.873 102.387,43.182 98.276,47.294 v1(98.276,47.465)
  Bottom w0.127: v2(92.641,49.995) 93.033,49.603 93.277,49.603 93.278,49.601 93.604,49.601 93.606,49.603 96.137,49.603 v1(98.276,47.465) ; EC1.100@94.357,28.836 94.357,33.168 v1(95.275,34.087)
MCU_GPIO55: EC1.102 U1.M14 | length 33.9
  Top Layer w0.127: U1.M14@93.041,50.395 v2(93.441,49.995) ; v1(95.25,32.233) 95.25,32.885 96.662,34.297 101.458,34.297 102.845,35.684 102.845,43.371 100.07,46.146 v1@100.07,47.136
  Bottom w0.127: v2(93.441,49.995) 97.37,49.995 99.944,47.421 99.944,47.379 100.07,47.253 v1@100.07,47.136 ; EC1.102@95.157,28.836 95.157,32.023 95.25,32.116 v1(95.25,32.233)
  other v1: 99.908,47.24
MCU_GPIO56: EC1.104 U1.M15 | length 31.5
  Top Layer w0.127: U1.M15@93.841,50.395 94.241,49.995 98.06,49.995 v1(98.638,49.418)
  Signal Layer 6 w0.127: v1(96.389,31.782) 96.554,31.947 97.621,31.947 98.268,32.595 98.268,33.099 102.54,37.37 102.54,46.84 100.935,48.445 99.61,48.445 v1(98.638,49.418)
  Bottom w0.127: EC1.104@95.957,28.836 95.957,31.351 v1(96.389,31.782)
MCU_GPIO57: EC1.106 U1.M16 | length 32.9
  Top Layer w0.127: U1.M16@94.641,50.395 98.471,50.395 100.357,48.508 100.827,48.508 102.565,46.77 102.565,43.974 103.073,43.466 103.073,35.589 101.552,34.068 97.254,34.068 v1(96.864,33.678)
  Bottom w0.127: EC1.106@96.757,28.836 96.757,31.23 96.903,31.376 96.903,32.062 96.622,32.343 96.622,33.319 96.864,33.561 v1(96.864,33.678)
MCU_GPIO58: J5.12 U1.L13 | length 61.7
  Top Layer w0.127: U1.L13@92.241,51.195 v2(92.641,50.795) ; J5.12@124.544,63.638 127.026,63.638 127.179,63.792 127.179,64.213 v1(127.229,64.262)
  Bottom w0.127: v2(92.641,50.795) 93.033,50.403 93.277,50.403 93.278,50.401 93.604,50.401 93.606,50.403 98.463,50.403 99.399,49.467 99.399,49.194 100.148,48.445 101.241,48.445 101.448,48.238 101.448,47.41 103.449,45.409 113.68,45.409 116.799,42.291 119.456,42.291 120.066,41.681 120.929,41.681 124.955,45.707 124.955,61.989 v1(127.229,64.262)
MCU_GPIO59: J6.12 U1.L14 | length 36.1
  Top Layer w0.127: U1.L14@93.041,51.195 v2(93.441,50.795)
  Top Layer w0.159: v1(120.599,42.189) 120.999,41.79 124.507,41.79 J6.12@124.544,41.752
  Bottom w0.127: v2(93.441,50.795) 98.394,50.795 99.627,49.562 99.627,49.289 100.243,48.673 101.335,48.673 101.676,48.332 101.676,47.505 103.543,45.638 113.775,45.638 116.893,42.52 120.269,42.52 v1(120.599,42.189)
MCU_GPIO60: EC2.125 U1.L15 | length 48.5
  Top Layer w0.127: U1.L15@93.841,51.195 94.251,50.785 98.449,50.785 99.068,50.166 100.013,49.221 v1(100.441,49.221) ; EC2.125@124.955,28.836 124.955,31.697 v1(125.421,32.163)
  Signal Layer 6 w0.127: v1(121.234,42.824) 123.357,40.702 123.357,32.659 124.297,31.719 124.976,31.719 v1(125.421,32.163)
  Bottom w0.127: v1(100.441,49.221) 101.111,49.221 101.905,48.427 101.905,47.6 103.638,45.867 113.87,45.867 114.39,45.346 114.399,45.346 116.92,42.824 v1(121.234,42.824)
MCU_GPIO61: EC2.126 U1.K16 | length 52
  Top Layer w0.127: U1.K16@94.641,51.995 96.521,51.995 v1(97.024,51.493)
  Signal Layer 3 w0.127: v1(97.024,51.493) 97.768,52.237 119.72,52.237 120.068,52.585 v1(120.112,52.585)
  Signal Layer 6 w0.127: v1(120.112,52.585) 120.229,52.585 120.354,52.46 120.398,52.46 122.171,50.687 123.814,49.044 123.814,33.777 124.507,33.084 v1(124.507,33.078)
  Bottom w0.127: v1(124.507,33.078) 124.964,32.62 124.964,28.845 EC2.126@124.955,28.836
MCU_GPIO62: EC2.127 U1.K15 | length 59.6
  Top Layer w0.127: U1.K15@93.841,51.995 94.251,51.585 96.194,51.585 v1(96.287,51.493) ; v1(125.396,33.128) 125.865,32.659 125.865,28.947 EC2.127@125.755,28.836
  Signal Layer 3 w0.127: v1(96.287,51.493) 97.068,52.273 97.481,52.273 97.674,52.466 119.282,52.466 119.858,53.042 120.769,53.042 121.201,52.61 127.021,52.61 127.838,51.793 127.838,50.202 v1(127.453,49.816)
  Signal Layer 6 w0.127: v1(125.396,33.128) 125.396,33.186 125.84,33.63 125.84,48.203 v1(127.453,49.816)
MCU_GPIO63: R158.1 R162.2 U1.K14 | length 27
  Top Layer w0.127: U1.K14@93.041,51.995 v2(93.441,51.595) v2@93.31,51.727 ; v1(97.811,51.493) 97.928,51.493 98.112,51.309 99.935,51.309 101.215,50.029 101.215,48.989 101.416,48.788 102.202,48.788 103.759,50.344 103.759,54.436 103.988,54.664 103.988,54.722 104.497,55.231 109.946,55.231 109.951,55.236 110.021,55.236 R158.1@110.183,55.398 ; R158.1@110.257,55.572 110.333,55.649 v1(110.333,56.649)
  Bottom w0.127: v2(93.441,51.595) 95.271,51.595 95.614,51.938 97.592,51.938 97.811,51.718 v1(97.811,51.493) ; v1(110.333,56.649) 110.336,56.649 110.653,56.966 R162.2@110.653,57.6
MCU_GPIO64: R147.2 R150.1 U1.K13 | length 29
  Top Layer w0.127: U1.K13@92.241,51.995 v2(92.641,51.595) ; v1(100.265,50.35) 100.986,49.629 100.986,48.894 101.321,48.559 102.297,48.559 103.988,50.25 103.988,54.341 104.629,54.982 110.702,54.982 111.081,55.361 111.286,55.361 R150.1@111.497,55.572 111.497,56.323 v1(111.172,56.649)
  Bottom w0.127: v2(92.641,51.595) 93.048,51.189 95.291,51.189 95.456,51.023 99.591,51.023 v1(100.265,50.35) ; v1(111.172,56.649) 111.172,57.181 R147.2@111.735,57.744
MCU_GPIO65: EC2.130 U1.K12 | length 60.5
  Top Layer w0.127: U1.K12@91.441,51.995 v2(91.841,51.595)
  Signal Layer 3 w0.127: v2(91.841,51.595) 92.235,51.989 95.163,51.989 96.03,51.122 96.103,51.048 99.21,51.048 99.818,51.657 108.89,51.657 109.664,50.883 127.031,50.883 127.184,51.035 v1(127.301,51.035)
  Signal Layer 6 w0.127: v1(126.691,33.67) 126.691,45.208 127.914,46.431 127.914,50.422 v1(127.301,51.035)
  Bottom w0.127: EC2.130@126.555,28.836 126.555,31.303 126.205,31.652 126.205,33.116 126.691,33.602 v1(126.691,33.67)
MCU_GPIO66: EC2.131 U1.K11 | length 59.1
  Top Layer w0.127: U1.K11@90.641,51.995 v2(91.041,51.595) ; v1(126.666,32.925) 127.355,32.236 EC2.131@127.355,28.836
  Signal Layer 3 w0.127: v2(91.041,51.595) 91.448,51.189 95.353,51.189 95.747,50.795 100.592,50.795 101.126,50.261 104.096,50.261 104.481,49.876 105.459,49.876 106.009,50.426 109.449,50.426 111.458,48.417 120.558,48.417 120.827,48.686 126.373,48.686 v1(127.402,47.657)
  Signal Layer 6 w0.127: v1(126.666,32.925) 126.069,33.522 126.069,46.324 v1(127.402,47.657)
MCU_GPIO67: EC2.132 U1.D15 | length 67.9
  Top Layer w0.127: U1.D15@93.841,56.795 94.251,57.204 96.531,57.204 101.704,62.377 115.827,62.377 120.767,57.436 125.904,57.436 130.073,53.266 130.073,36.917 v1(127.885,34.729)
  Bottom w0.127: EC2.132@127.355,28.836 127.355,34.199 v1(127.885,34.729)
MCU_GPIO68: EC2.133 U1.C16 | length 67.5
  Top Layer w0.127: U1.C16@94.641,57.595 96.293,57.595 98.044,59.346 v1(98.044,59.868) ; v1@127.943,31.963 127.943,29.047 EC2.133@128.155,28.836
  Signal Layer 3 w0.127: v1(98.044,59.868) 98.23,60.054 103.494,60.054 104.174,59.374 108.144,59.374 108.925,60.154 119.452,60.154 120.112,60.814 v1(126.818,60.814)
  Signal Layer 6 w0.127: v1(126.818,60.814) 127.047,60.586 127.047,52.262 127.923,51.385 128.372,50.936 128.372,43.917 127.356,42.901 127.356,38.691 127.364,38.683 127.364,33.459 127.356,33.451 127.356,32.667 v1(127.859,32.163)
MCU_GPIO69: R148.1 U1.B16 | length 20.2
  Top Layer w0.127: U1.B16@94.641,58.395 94.715,58.395 94.836,58.516 96.522,58.516 96.874,58.868 v1(96.874,59.983) ; R148.1@105.975,51.83 106.075,51.83 106.312,52.067 106.312,52.082 106.566,52.336 106.566,53.79 v1(106.1,54.256)
  Bottom w0.127: v1(96.874,59.983) 97.343,60.452 102.87,60.452 103.59,59.732 103.59,57.195 106.1,54.685 v1(106.1,54.256)
MCU_GPIO70: R149.1 R161.2 U1.C15 | length 19.8
  Top Layer w0.127: U1.C15@93.841,57.595 94.241,57.995 96.033,57.995 v1(96.109,58.071) ; v1(104.648,54.254) 104.648,53.49 105.066,53.072 R149.1@105.975,53.072
  Bottom w0.127: v1(96.109,58.071) 97.009,58.071 98.703,59.764 103.001,59.764 103.361,59.405 103.361,57.1 104.648,55.813 v1(104.648,54.254) 104.661,54.241 104.661,53.33 R161.2@104.898,53.094
MCU_GPIO71: R130.1 R154.1 U1.B15 | length 27.3
  Top Layer w0.127: U1.B15@93.841,58.395 94.232,58.785 94.232,59.58 95.18,60.528 v1(95.225,60.528) ; v1(104.439,51.039) 105.426,51.039 105.875,50.589 R154.1@105.975,50.589 ; R154.1@106.194,50.648 R154.1@106.294,50.648
  Signal Layer 3 w0.127: v1(95.225,60.528) 96.298,61.602 104.353,61.602 104.76,61.195 v1(104.796,61.195)
  Signal Layer 6 w0.127: v1@104.515,50.828 104.098,51.245 104.098,56.362 104.796,57.06 v1(104.796,61.195)
  Bottom w0.127: v1(104.439,51.039) 105.327,51.039 105.862,50.504 R130.1@105.962,50.504
MCU_GPIO72: EC2.139 R62.1 U1.A15 | length 91.4
  Top Layer w0.127: U1.A15@93.841,59.195 93.873,59.226 93.873,60.98 v1(93.904,61.011) ; EC2.139@130.555,28.836 130.628,28.909 v1(130.628,32.138)
  Signal Layer 3 w0.127: v1(93.904,61.011) 93.984,61.011 95.033,62.059 107.546,62.059 107.889,61.716 131.11,61.716 135.022,57.805 139.426,57.805 140.106,57.125 v1(140.106,56.845)
  Signal Layer 6 w0.127: v1(130.628,32.138) 130.933,31.833 140.774,31.833 141.398,32.457 141.398,47.274 139.836,48.835 139.836,55.747 140.106,56.018 v1(140.106,56.845)
  Bottom w0.127: v1(140.106,56.845) R62.1@140.106,57.769
MCU_GPIO73: EC2.140 U1.D14 | length 66.1
  Top Layer w0.127: U1.D14@93.041,56.795 v2(93.441,57.195)
  Signal Layer 3 w0.127: v1(98.23,57.296) 98.23,57.304 98.667,57.741 100.275,57.741 100.605,57.411 102.33,57.411 103.038,58.12 123.137,58.12 123.719,57.538 v1(127.809,57.538)
  Signal Layer 6 w0.127: v1(127.809,57.538) 127.809,56.122 130.023,53.908 130.023,34.14 v1(130.577,33.586)
  Bottom w0.127: v2(93.441,57.195) 93.505,57.258 98.192,57.258 v1(98.23,57.296) ; EC2.140@130.555,28.836 130.555,31.583 130.023,32.115 130.023,33.031 v1(130.577,33.586)
MCU_GPIO74: EC2.141 U1.C14 | length 70.9
  Top Layer w0.127: U1.C14@93.041,57.595 v2(93.441,57.995) ; v1(130.886,32.868) 131.355,32.399 EC2.141@131.355,28.836
  Signal Layer 3 w0.127: v1(96.383,59.319) 96.867,59.319 97.88,60.333 103.611,60.333 104.341,59.602 106.516,59.602 108.173,61.259 127.025,61.259 127.241,61.043 v1(127.885,61.043)
  Signal Layer 6 w0.127: v1(127.885,61.043) 127.885,59.748 128.991,58.642 128.991,55.263 130.251,54.003 130.251,35.731 131.129,34.854 131.129,33.11 v1(130.886,32.868)
  Bottom w0.127: v2(93.441,57.995) 95.218,57.995 v1@96.462,59.239
MCU_GPIO75: U1.B14
MCU_GPIO76: EC2.143 U1.A14 | length 72.2
  Top Layer w0.127: U1.A14@93.041,59.195 93.041,60.083 v1(93.366,60.408) ; EC2.143@132.155,28.836 132.155,31.5 131.936,31.719 131.936,33.361 v1(132.381,33.806)
  Signal Layer 3 w0.127: v1(93.366,60.408) 94.187,60.408 95.609,61.83 107.452,61.83 107.794,61.488 129.19,61.488 v1(129.794,60.884)
  Signal Layer 6 w0.127: v1(129.794,60.884) 130.374,60.304 130.374,54.903 131.936,53.341 131.936,34.25 v1(132.381,33.806)
MCU_GPIO77: EC2.144 U1.F13 | length 69.9
  Top Layer w0.127: U1.F13@92.241,55.195 v2(92.641,55.595)
  Signal Layer 3 w0.127: v1(97.151,56.319) 97.151,56.973 98.148,57.97 100.686,57.97 101.016,57.639 102.235,57.639 102.944,58.348 123.232,58.348 123.562,58.018 126.532,58.018 126.534,58.02 129.345,58.02 129.523,57.843 v1(129.637,57.843)
  Signal Layer 6 w0.127: v1(129.637,57.843) 129.637,54.993 131.479,53.152 131.479,33.217 v1(132.381,32.316)
  Bottom w0.127: v2(92.641,55.595) 93.035,55.989 95.198,55.989 95.236,55.95 96.209,55.95 96.578,56.319 v1(97.151,56.319) ; EC2.144@132.155,28.836 132.155,32.09 v1(132.381,32.316) ; v1@132.406,32.29 v1@132.431,32.316
MCU_GPIO78: EC2.128 U1.E13 | length 64.3
  Top Layer w0.127: U1.E13@92.241,55.995 v2(92.641,56.395)
  Signal Layer 3 w0.127: v1(97.841,56.718) 98.402,56.718 99.135,55.986 103.722,55.986 105.572,57.836 119.374,57.836 120.2,57.009 125.517,57.009 v1(126.081,56.446)
  Signal Layer 6 w0.127: v1(125.197,34.036) 125.221,34.036 125.586,34.401 125.586,52.84 126.081,53.336 v1(126.081,56.446)
  Bottom w0.127: v2(92.641,56.395) 93.048,56.801 95.198,56.801 95.291,56.895 96.419,56.895 96.551,56.763 97.796,56.763 v1(97.841,56.718) ; v1(125.197,34.036) 125.865,33.367 125.865,28.836 EC2.128@125.755,28.836
MCU_GPIO79: EC2.146 U1.D13 | length 71.4
  Top Layer w0.127: U1.D13@92.241,56.795 v2(92.641,57.195)
  Signal Layer 3 w0.127: v1(98.726,58.706) 99.616,59.596 103.304,59.596 103.984,58.916 108.334,58.916 109.114,59.697 119.641,59.697 120.086,60.141 128.594,60.141 v1(128.952,59.784)
  Signal Layer 6 w0.127: v1(128.952,59.784) 128.952,59.651 129.619,58.984 130.145,58.457 130.145,54.808 131.707,53.246 131.707,33.734 v1(132.381,33.061)
  Bottom w0.127: v2(92.641,57.195) 93.035,57.589 93.604,57.589 93.606,57.587 97.606,57.587 v1(98.726,58.706) ; v1(132.381,33.061) 132.955,32.487 EC2.146@132.955,28.836
MCU_GPIO80: EC2.147 U1.A13 | length 77.6
  Top Layer w0.127: U1.A13@92.241,59.195 92.241,59.674 92.432,59.864 92.432,60.693 94.064,62.325 94.347,62.325 v1(94.411,62.389) ; EC2.147@133.755,28.836 133.755,31.861 v1(134.209,32.316)
  Signal Layer 3 w0.127: v1(94.411,62.389) 94.734,62.713 96.282,62.713 96.389,62.605 107.659,62.605 108.027,62.237 131.747,62.237 132.078,61.907 v1(132.101,61.907)
  Signal Layer 6 w0.127: v1(132.101,61.907) 130.831,60.637 130.831,55.106 131.75,54.188 131.75,54.174 132.512,53.412 132.512,36.017 132.939,35.59 132.939,33.586 v1(134.209,32.316)
MCU_GPIO81: EC2.148 U1.F12 | length 70.5
  Top Layer w0.127: U1.F12@91.441,55.195 v2(91.841,55.595)
  Signal Layer 3 w0.127: v2(91.841,55.595) 92.235,55.201 92.478,55.201 94.128,55.201 94.598,54.731 98.837,54.731 99.173,55.067 104.096,55.067 105.832,56.803 107.957,56.803 109.445,55.315 126.549,55.315 126.555,55.321 131.478,55.321 132.037,54.762 v1(132.131,54.762)
  Signal Layer 6 w0.127: v1(132.131,54.762) 134.082,52.811 134.082,39.224 134.032,39.174 133.397,38.539 133.397,34.619 v1(134.209,33.806)
  Bottom w0.127: EC2.148@133.755,28.836 133.755,33.351 v1(134.209,33.806)
MCU_GPIO82: EC2.149 U1.E12 | length 71.4
  Top Layer w0.127: U1.E12@91.441,55.995 v2(91.841,56.395) ; v1(134.209,34.551) 134.679,34.081 134.679,28.96 EC2.149@134.555,28.836
  Signal Layer 3 w0.127: v2(91.841,56.395) 92.235,56.001 94.325,56.001 94.686,55.64 95.348,54.978 98.761,54.978 99.078,55.296 104.001,55.296 105.759,57.053 108.031,57.053 109.54,55.544 126.455,55.544 126.461,55.55 132.131,55.55 132.957,54.724 v1(132.957,54.577)
  Signal Layer 6 w0.127: v1(132.957,54.577) 133.104,54.577 134.336,53.344 134.336,39.047 133.625,38.335 133.625,35.135 v1(134.209,34.551)
MCU_GPIO83: EC2.150 U1.D12 | length 84.3
  Top Layer w0.127: U1.D12@91.441,56.795 v2(91.841,57.195)
  Signal Layer 3 w0.127: v1(93.345,62.687) 93.345,63.302 93.842,63.799 95.085,63.799 95.63,64.344 97.324,64.344 97.513,64.154 101.299,64.154 102.086,63.367 132.571,63.367 v1(132.889,63.05)
  Signal Layer 6 w0.127: v1(132.889,63.05) 132.876,63.037 132.876,61.945 131.06,60.129 131.06,55.201 132.156,54.105 132.156,54.091 132.74,53.507 132.74,36.119 133.168,35.691 133.168,34.102 v1(134.209,33.061)
  Bottom w0.127: v2(91.841,57.195) 92.235,57.589 92.235,61.577 v1(93.345,62.687) ; v1(134.209,33.061) 134.654,32.616 134.654,28.935 EC2.150@134.555,28.836
MCU_GPIO84: EC2.151 R63.1 U1.D9 | length 78.9
  Top Layer w0.127: U1.D9@89.041,56.795 v2@89.43,57.184 ; EC2.151@135.355,28.836 135.355,31.988 v1@135.683,32.316
  Signal Layer 3 w0.127: v2(89.441,57.195) 89.835,56.801 93.604,56.801 93.849,56.801 94.607,56.043 95.443,55.207 98.666,55.207 98.984,55.524 103.907,55.524 105.679,57.297 108.11,57.297 109.635,55.773 126.36,55.773 126.366,55.778 132.69,55.778 v1(133.274,55.194)
  Signal Layer 6 w0.127: v1(133.274,55.194) 134.565,53.903 134.565,38.843 133.854,38.132 133.854,36.869 134.768,35.955 134.768,33.128 v1(135.581,32.316)
  Bottom w0.127: R63.1@130.885,57.769 130.831,57.716 130.831,57.119 132.756,55.194 v1(133.274,55.194)
MCU_GPIO85: EC2.152 U1.C9 | length 77.7
  Top Layer w0.127: U1.C9@89.041,57.595 v2(89.441,57.995)
  Signal Layer 3 w0.127: v2(89.441,57.995) 90.013,58.567 98.179,58.567 98.548,58.198 100.78,58.198 101.111,57.868 102.14,57.868 102.849,58.577 108.317,58.577 109.151,59.411 123.749,59.411 124.176,58.984 125.288,58.984 128.757,58.984 128.767,58.973 129.136,58.973 129.146,58.984 132.891,58.984 134.895,56.979 v1(134.895,56.903)
  Signal Layer 6 w0.127: v1(134.895,56.903) 134.819,56.827 134.819,38.774 134.082,38.038 134.082,36.964 134.997,36.049 134.997,34.39 v1(135.581,33.806)
  Bottom w0.127: EC2.152@135.355,28.836 135.238,28.952 135.238,31.928 134.971,32.195 134.971,33.196 v1(135.581,33.806)
MCU_GPIO86: EC2.153 U1.B9 | length 91.2
  Top Layer w0.127: U1.B9@89.041,58.395 89.451,58.804 89.451,59.852 90.331,60.732 90.331,63.661 v1(90.348,63.678) ; v1@135.733,32.976 136.155,32.555 EC2.153@136.155,28.836
  Signal Layer 3 w0.127: v1(90.348,63.678) 90.418,63.678 93.918,67.177 108.163,67.177 109.852,65.488 135.323,65.488 135.595,65.761 v1(135.712,65.761)
  Signal Layer 6 w0.127: v1(135.581,33.061) 136.103,33.582 136.103,57.194 135.304,57.992 135.304,65.353 v1(135.712,65.761)
MCU_GPIO87: EC2.154 U1.A9 | length 93
  Top Layer w0.127: v1(88.688,61.907) 88.688,61.894 89.201,61.381 89.201,60.004 89.041,59.845 U1.A9@89.041,59.195
  Signal Layer 3 w0.127: v1(88.688,61.907) 88.947,61.907 89.277,62.237 89.277,64.74 90.868,66.332 92.668,66.332 93.742,67.406 114.81,67.406 115.172,67.767 v1(135.077,67.767)
  Signal Layer 6 w0.127: v1(135.077,67.767) 135.076,67.766 135.076,57.898 135.848,57.126 135.848,35.046 v1(135.47,34.669)
  Bottom w0.127: v1(135.47,34.669) 136.178,33.961 136.178,28.859 EC2.154@136.155,28.836
MCU_GPIO88: EC2.155 U1.B6 | length 89.9
  Top Layer w0.127: U1.B6@86.641,58.395 86.221,58.815 86.232,58.825 86.232,60.005 86.436,60.209 86.436,61.2 87.057,61.821 v1(87.186,61.821) ; EC2.155@136.955,28.836 136.955,31.501 136.711,31.744 136.711,33.302 v1(137.212,33.802)
  Signal Layer 3 w0.127: v1(87.186,61.821) 87.503,61.504 87.503,60.475 88.276,59.701 91.095,59.701 94.373,62.98 96.407,62.98 96.553,62.834 107.754,62.834 108.122,62.465 135.149,62.465 v1(135.835,61.78)
  Signal Layer 6 w0.127: v1(135.835,61.78) 135.835,61.697 136.56,60.972 136.56,34.454 v1(137.212,33.802)
MCU_GPIO89: EC2.156 U1.C6 | length 88.3
  Top Layer w0.127: v2(86.241,57.995) U1.C6@86.641,57.595
  Signal Layer 3 w0.127: v1(85.964,60.596) 87.088,59.473 91.644,59.473 94.02,61.849 94.499,61.849 94.938,62.288 107.641,62.288 107.984,61.945 131.301,61.945 131.873,61.373 135.443,61.373 135.748,61.068 v1(135.784,61.068)
  Signal Layer 6 w0.127: v1(135.784,61.068) 135.796,61.068 136.331,60.533 136.331,33.934 v1@137.156,33.109
  Bottom w0.127: v1@86.064,60.596 86.064,59.592 86.241,59.415 v2(86.241,57.995) ; EC2.156@136.955,28.836 136.955,31.044 136.622,31.376 136.622,32.443 137.212,33.032 v1(137.212,33.059)
MCU_GPIO90: EC2.159 U1.D6 | length 110.8
  Top Layer w0.127: v2(86.241,57.195) U1.D6@86.641,56.795 ; v1(137.871,33.32) 138.555,32.637 EC2.159@138.555,28.836
  Signal Layer 3 w0.127: v1(86.233,69.596) 88.246,71.609 92.786,71.609 93.967,72.791 97.623,72.791 98.06,73.228 121.101,73.228 121.242,73.087 134.834,73.087 135.108,73.362 v1(135.225,73.362)
  Signal Layer 6 w0.127: v1(85.979,61.519) 85.979,62.113 85.242,62.85 85.242,68.605 v1(86.233,69.596) ; v1(135.225,73.362) 135.225,71.457 136.788,69.894 136.788,34.856 137.871,33.773 v1(137.871,33.32)
  Bottom w0.127: v1(85.979,61.519) 85.506,61.046 85.506,59.959 85.835,59.631 85.835,57.601 v2(86.241,57.195)
MCU_GPIO91: EC2.160 U1.E6 | length 86.2
  Top Layer w0.127: v2(86.241,56.395) U1.E6@86.641,55.995
  Signal Layer 3 w0.127: v2(86.241,56.395) 86.635,56.001 87.463,56.001 88.667,57.205 88.667,58.238 89.075,58.646 89.769,58.646 89.918,58.795 98.186,58.795 99.216,59.825 99.844,59.825 103.399,59.825 104.079,59.145 108.239,59.145 109.019,59.925 119.547,59.925 119.991,60.37 132.133,60.37 135.378,57.125 v1(138.557,57.125)
  Signal Layer 6 w0.127: v1(138.557,57.125) 138.557,57.078 138.248,56.769 138.248,34.517 v1(138.959,33.806)
  Bottom w0.127: EC2.160@138.555,28.836 138.406,28.984 138.406,33.159 v1@138.883,33.636
MCU_GPIO92: EC2.161 U1.A5 | length 102.6
  Top Layer w0.127: U1.A5@85.841,59.195 85.841,59.624 85.34,60.126 85.34,61.837 86.439,62.937 86.903,62.937 v1(87.423,63.456) ; v1(138.937,32.912) 139.404,32.445 139.404,28.836 EC2.161@139.355,28.836
  Signal Layer 3 w0.127: v1(87.423,63.456) 87.816,63.85 87.816,67.293 90.888,70.365 93.243,70.365 93.688,70.809 98.399,70.809 102.234,70.809 103.58,69.463 115.013,69.463 115.533,68.942 137.712,68.942 v1(137.744,68.91)
  Signal Layer 6 w0.127: v1(137.744,68.91) 137.744,68.888 138.013,68.62 138.013,34.119 138.257,33.875 138.257,33.591 v1(138.937,32.912)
